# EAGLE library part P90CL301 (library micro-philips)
MICROCONTROLLER
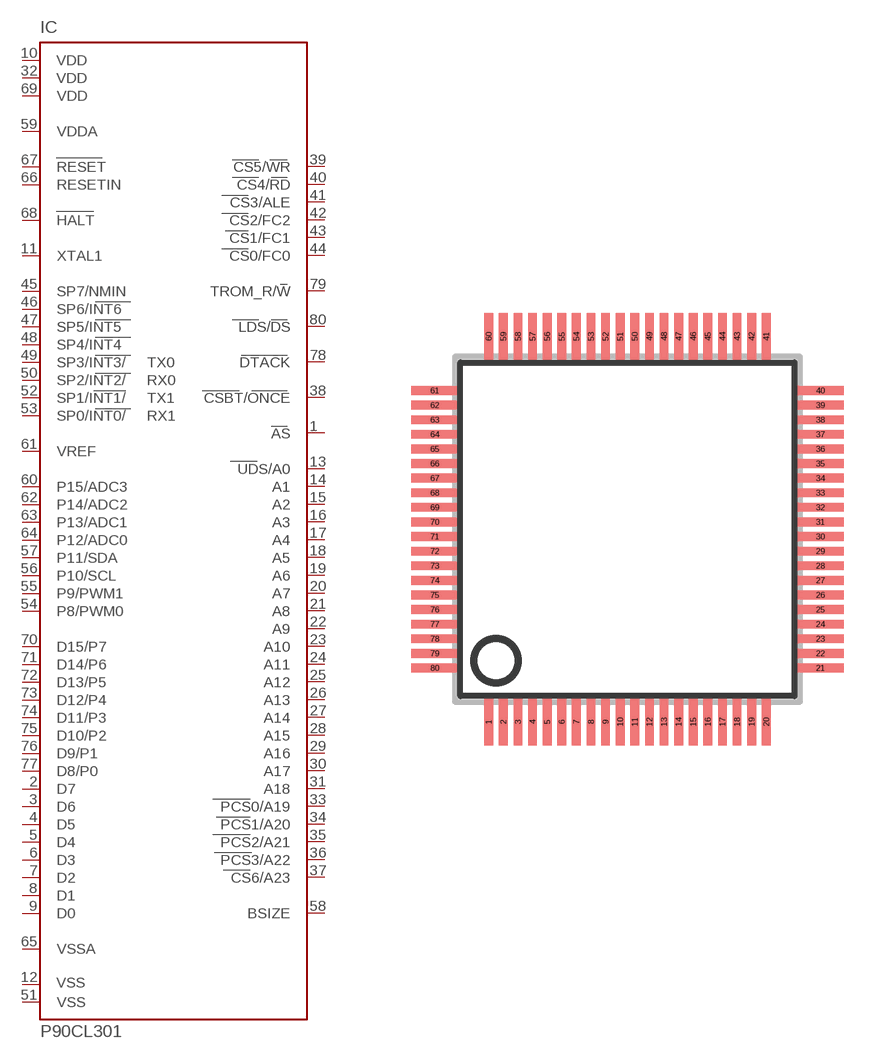
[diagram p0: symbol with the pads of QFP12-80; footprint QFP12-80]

Designator prefix IC

## P90CL301 (OC_FARNELL: unknown; OC_NEWARK: unknown)  [QFP12-80]
1  AS  out
2  D7
3  D6
4  D5
5  D4
6  D3
7  D2
8  D1
9  D0
10  VDD  pwr
11  XTAL1  in
12  VSS  pwr
13  UDS/A0  out
14  A1  out
15  A2  out
16  A3  out
17  A4  out
18  A5  out
19  A6  out
20  A7  out
21  A8  out
22  A9  out
23  A10  out
24  A11  out
25  A12  out
26  A13  out
27  A14  out
28  A15  out
29  A16  out
30  A17  out
31  A18  out
32  VDD  pwr
33  PCS0/A19  out
34  PCS1/A20  out
35  PCS2/A21  out
36  PCS3/A22  out
37  CS6/A23  out
38  CSBT/ONCE
39  CS5/WR  out
40  CS4/RD  out
41  CS3/ALE  out
42  CS2/FC2
43  CS1/FC1
44  CS0/FC0
45  SP7/NMIN
46  SP6/INT6
47  SP5/INT5
48  SP4/INT4
49  SP3/INT3/
50  SP2/INT2/
51  VSS  pwr
52  SP1/INT1/
53  SP0/INT0/
54  P8/PWM0
55  P9/PWM1
56  P10/SCL
57  P11/SDA
58  BSIZE  out
59  VDDA  pwr
60  P15/ADC3
61  VREF  pas
62  P14/ADC2
63  P13/ADC1
64  P12/ADC0
65  VSSA  pwr
66  RESETIN  in
67  RESET
68  HALT
69  VDD  pwr
70  D15/P7
71  D14/P6
72  D13/P5
73  D12/P4
74  D11/P3
75  D10/P2
76  D9/P1
77  D8/P0
78  DTACK  out
79  TROM_R/W
80  LDS/DS  out

## Footprint QFP12-80 (pad centres in mm)
Quad Flat Pack
smd 0.3 x 1.6: 1 -4.75,-6.6; 2 -4.25,-6.6; 3 -3.75,-6.6; 4 -3.25,-6.6; 5 -2.75,-6.6; 6 -2.25,-6.6; 7 -1.75,-6.6; 8 -1.25,-6.6; 9 -0.75,-6.6; 10 -0.25,-6.6; 11 0.25,-6.6; 12 0.75,-6.6; 13 1.25,-6.6; 14 1.75,-6.6; 15 2.25,-6.6; 16 2.75,-6.6; 17 3.25,-6.6; 18 3.75,-6.6; 19 4.25,-6.6; 20 4.75,-6.6; 41 4.75,6.6; 42 4.25,6.6; 43 3.75,6.6; 44 3.25,6.6; 45 2.75,6.6; 46 2.25,6.6; 47 1.75,6.6; 48 1.25,6.6; 49 0.75,6.6; 50 0.25,6.6; 51 -0.25,6.6; 52 -0.75,6.6; 53 -1.25,6.6; 54 -1.75,6.6; 55 -2.25,6.6; 56 -2.75,6.6; 57 -3.25,6.6; 58 -3.75,6.6; 59 -4.25,6.6; 60 -4.75,6.6
smd 1.6 x 0.3: 21 6.6,-4.75; 22 6.6,-4.25; 23 6.6,-3.75; 24 6.6,-3.25; 25 6.6,-2.75; 26 6.6,-2.25; 27 6.6,-1.75; 28 6.6,-1.25; 29 6.6,-0.75; 30 6.6,-0.25; 31 6.6,0.25; 32 6.6,0.75; 33 6.6,1.25; 34 6.6,1.75; 35 6.6,2.25; 36 6.6,2.75; 37 6.6,3.25; 38 6.6,3.75; 39 6.6,4.25; 40 6.6,4.75; 61 -6.6,4.75; 62 -6.6,4.25; 63 -6.6,3.75; 64 -6.6,3.25; 65 -6.6,2.75; 66 -6.6,2.25; 67 -6.6,1.75; 68 -6.6,1.25; 69 -6.6,0.75; 70 -6.6,0.25; 71 -6.6,-0.25; 72 -6.6,-0.75; 73 -6.6,-1.25; 74 -6.6,-1.75; 75 -6.6,-2.25; 76 -6.6,-2.75; 77 -6.6,-3.25; 78 -6.6,-3.75; 79 -6.6,-4.25; 80 -6.6,-4.75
